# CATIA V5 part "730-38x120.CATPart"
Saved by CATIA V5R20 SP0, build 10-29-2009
Part number: 730-38x120
Definition: NONE
Nomenclature: 730-38x120
Source: Unknown
Description: 730-38x120
Bounding box of the stored display mesh (mm): x -23 to 23, y -22.5 to 22.5, z 0 to 120
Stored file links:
  C:\Users\Utente\Desktop\IO LAVORO\3D X SITO CF\X SITO\730\730-38x120.CATPart
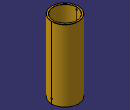
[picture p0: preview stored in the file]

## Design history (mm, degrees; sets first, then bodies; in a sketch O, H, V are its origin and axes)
Body1 "730-38x120" (main body)
  Solid1: solid without history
